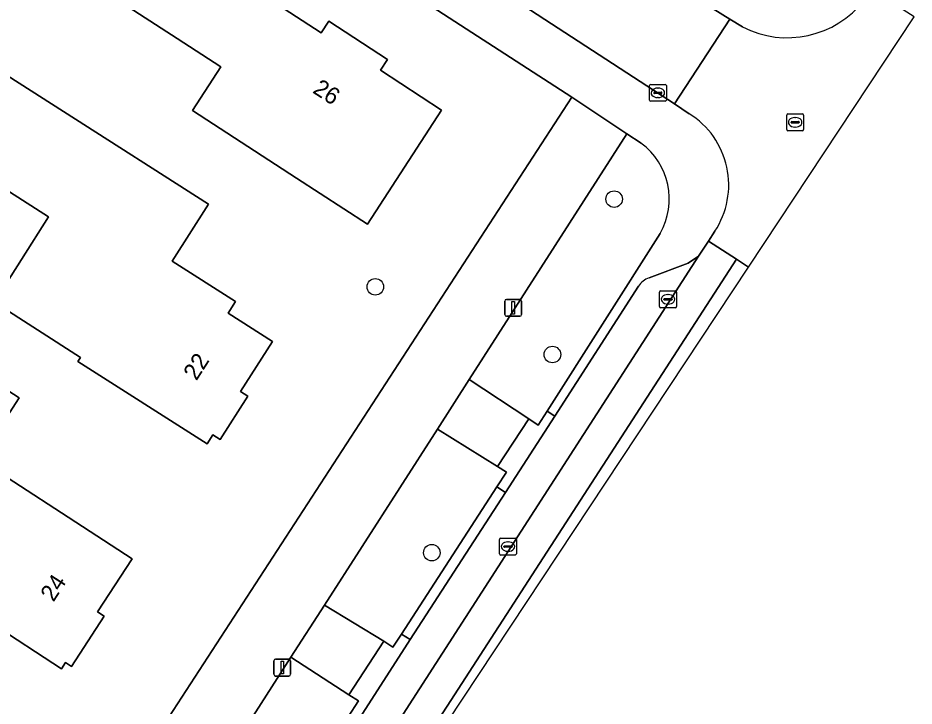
# Model space of a CAD drawing. Extents: x 161139 to 161601, y 381708 to 382245.
# Drawn here: x 161442 to 161495.1, y 381929.2 to 381969.9 of the extents above; entities that cross this region are included whole.
import ezdxf

# ---------------------------------------------------------------- set-up
doc = ezdxf.new("R2010")
doc.units = 0
for name, color, linetype in [('IMGEO_Boom', 7, 'Continuous'), ('IMGEO_Erf', 7, 'Continuous'), ('IMGEO_Groenvoorziening', 7, 'Continuous'), ('IMGEO_Kolk', 7, 'Continuous'), ('IMGEO_Lichtmast', 7, 'Continuous'), ('IMGEO_Pand', 7, 'Continuous'), ('IMGEO_Pand_nummerreeks', 7, 'Continuous'), ('IMGEO_Parkeervlak_open', 7, 'Continuous'), ('IMGEO_Rijbaan_lokaal_gesloten', 7, 'Continuous'), ('IMGEO_Rijbaan_lokaal_open', 7, 'Continuous'), ('IMGEO_Rioolput', 7, 'Continuous'), ('IMGEO_Voetpad_open', 7, 'Continuous')]:
    doc.layers.add(name, color=color, linetype=linetype)

msp = doc.modelspace()

# ---------------------------------------------------------------- linework, layer by layer
at = {"layer": 'IMGEO_Boom'}
for centre in [(161477.319, 381959.197), (161463.178, 381954.004), (161473.664, 381949.997), (161466.524, 381938.263)]:
    msp.add_circle(centre, 0.489, dxfattribs=at)
at = {"layer": 'IMGEO_Erf'}
msp.add_lwpolyline([(161430.666, 381897.334), (161474.804, 381965.241), (161421.048, 382000)], dxfattribs=at)
for points in [[(161449.552, 381975.564), (161456.544, 381971.017), (161456.666, 381971.205), (161459.982, 381969.048), (161460.425, 381969.728), (161463.898, 381967.469), (161463.48, 381966.826), (161467.104, 381964.469), (161462.709, 381957.712), (161458.518, 381960.439), (161452.348, 381964.452), (161454.026, 381967.032), (161451.457, 381968.703), (161446.982, 381971.614)], [(161436.113, 381969.868), (161453.299, 381958.899), (161451.149, 381955.529), (161454.905, 381953.132), (161454.472, 381952.454), (161457.1, 381950.777), (161455.205, 381947.808), (161455.632, 381947.535), (161453.984, 381944.959), (161453.554, 381945.234), (161453.216, 381944.706), (161445.564, 381949.575), (161445.725, 381949.828), (161440.611, 381953.092), (161443.837, 381958.147), (161436.391, 381962.9), (161436.43, 381962.961), (161433.072, 381965.105)], [(161426.297, 381954.589), (161427.683, 381956.735), (161435.118, 381951.933), (161442.093, 381947.428), (161439.732, 381943.773), (161444.594, 381940.628), (161448.782, 381937.896), (161446.736, 381934.759), (161447.131, 381934.501), (161445.19, 381931.527), (161444.844, 381931.753), (161444.6, 381931.379), (161440.412, 381934.111), (161435.544, 381937.289), (161436.694, 381939.07), (161433.36, 381941.223), (161435.339, 381944.288), (161431.697, 381946.644), (161432.758, 381948.284), (161433.731, 381949.788)]]:
    msp.add_lwpolyline(points, close=True, dxfattribs=at)
at = {"layer": 'IMGEO_Groenvoorziening'}
msp.add_lwpolyline([(161478.909, 381962.515), (161478.068, 381963.057), (161468.743, 381948.527), (161472.261, 381946.18), (161472.824, 381945.809), (161473.355, 381946.644), (161480.039, 381957.163)], dxfattribs=at)
for points in [[(161464.222, 381932.663), (161464.734, 381933.448), (161470.374, 381942.161), (161470.955, 381943.032), (161470.422, 381943.36), (161466.851, 381945.579), (161460.162, 381935.157), (161463.677, 381933.019)], [(161455.625, 381919.283), (161456.096, 381920.062), (161461.576, 381928.548), (161462.19, 381929.494), (161461.612, 381929.854), (161458.183, 381932.073), (161451.6, 381921.815), (161455.089, 381919.607)]]:
    msp.add_lwpolyline(points, close=True, dxfattribs=at)
msp.add_arc((161476.493, 381959.21), 4.094, 330.0081, 53.8361, dxfattribs=at)
at = {"layer": 'IMGEO_Kolk'}
for p, q in [((161479.408, 381965.065), (161479.408, 381965.917)), ((161479.483, 381965.991), (161480.335, 381965.991)), ((161480.409, 381965.917), (161480.409, 381965.065)), ((161479.667, 381965.485), (161479.667, 381965.497)), ((161480.105, 381965.448), (161479.707, 381965.448)), ((161479.71, 381965.534), (161480.108, 381965.534)), ((161479.896, 381965.771), (161479.921, 381965.771)), ((161480.151, 381965.497), (161480.151, 381965.485)), ((161480.335, 381964.991), (161479.483, 381964.991)), ((161479.919, 381965.211), (161479.894, 381965.211)), ((161480.008, 381952.84), (161480.008, 381953.692)), ((161480.083, 381953.766), (161480.935, 381953.766)), ((161481.009, 381953.692), (161481.009, 381952.84)), ((161480.267, 381953.26), (161480.267, 381953.272)), ((161480.705, 381953.223), (161480.307, 381953.223)), ((161480.31, 381953.309), (161480.708, 381953.309)), ((161480.496, 381953.546), (161480.521, 381953.546)), ((161480.751, 381953.272), (161480.751, 381953.26)), ((161480.935, 381952.766), (161480.083, 381952.766)), ((161480.519, 381952.986), (161480.494, 381952.986)), ((161470.529, 381938.199), (161470.529, 381939.051)), ((161470.604, 381939.125), (161471.456, 381939.125)), ((161471.017, 381938.905), (161471.042, 381938.905)), ((161471.53, 381939.051), (161471.53, 381938.199)), ((161470.788, 381938.619), (161470.788, 381938.631)), ((161471.226, 381938.582), (161470.828, 381938.582)), ((161470.831, 381938.668), (161471.229, 381938.668)), ((161471.04, 381938.345), (161471.015, 381938.345)), ((161471.272, 381938.631), (161471.272, 381938.619)), ((161471.456, 381938.125), (161470.604, 381938.125))]:
    msp.add_line(p, q, dxfattribs=at)
for points in [[(161479.408, 381965.065), (161479.408, 381965.917)], [(161479.483, 381965.991), (161480.335, 381965.991)], [(161480.409, 381965.917), (161480.409, 381965.065)], [(161480.335, 381964.991), (161479.483, 381964.991)], [(161480.008, 381952.84), (161480.008, 381953.692)], [(161480.083, 381953.766), (161480.935, 381953.766)], [(161481.009, 381953.692), (161481.009, 381952.84)], [(161480.935, 381952.766), (161480.083, 381952.766)], [(161470.529, 381938.199), (161470.529, 381939.051)], [(161470.604, 381939.125), (161471.456, 381939.125)], [(161471.53, 381939.051), (161471.53, 381938.199)], [(161471.456, 381938.125), (161470.604, 381938.125)]]:
    msp.add_lwpolyline(points, dxfattribs=at)
for centre, radius, start, end in [((161479.485, 381965.915), 0.0765, 91.552, 178.448), ((161479.485, 381965.915), 0.0765, 91.552, 178.448), ((161480.333, 381965.915), 0.0765, 1.552, 88.448), ((161480.333, 381965.915), 0.0765, 1.552, 88.448), ((161479.707, 381965.494), 0.0403, 85.8775, 175.7526), ((161479.704, 381965.484), 0.0366, 178.938, 274.7102), ((161480.108, 381965.491), 0.043, 264.8664, 352.4533), ((161480.112, 381965.496), 0.0386, 1.7309, 96.639), ((161479.485, 381965.067), 0.0765, 181.552, 268.448), ((161479.485, 381965.067), 0.0765, 181.552, 268.448), ((161480.333, 381965.067), 0.0765, 271.552, 358.448), ((161480.333, 381965.067), 0.0765, 271.552, 358.448), ((161480.085, 381953.69), 0.0765, 91.552, 178.448), ((161480.085, 381953.69), 0.0765, 91.552, 178.448), ((161480.933, 381953.69), 0.0765, 1.552, 88.448), ((161480.933, 381953.69), 0.0765, 1.552, 88.448), ((161480.307, 381953.269), 0.0403, 85.8775, 175.7526), ((161480.304, 381953.259), 0.0366, 178.938, 274.7102), ((161480.708, 381953.266), 0.043, 264.8664, 352.4533), ((161480.712, 381953.271), 0.0386, 1.7309, 96.639), ((161480.085, 381952.842), 0.0765, 181.552, 268.448), ((161480.085, 381952.842), 0.0765, 181.552, 268.448), ((161480.933, 381952.842), 0.0765, 271.552, 358.448), ((161480.933, 381952.842), 0.0765, 271.552, 358.448), ((161470.606, 381939.049), 0.0765, 91.552, 178.448), ((161470.606, 381939.049), 0.0765, 91.552, 178.448), ((161471.454, 381939.049), 0.0765, 1.552, 88.448), ((161471.454, 381939.049), 0.0765, 1.552, 88.448), ((161470.828, 381938.628), 0.0403, 85.8775, 175.7526), ((161470.825, 381938.618), 0.0366, 178.938, 274.7102), ((161471.229, 381938.625), 0.043, 264.8664, 352.4533), ((161471.233, 381938.63), 0.0386, 1.7309, 96.639), ((161470.606, 381938.201), 0.0765, 181.552, 268.448), ((161470.606, 381938.201), 0.0765, 181.552, 268.448), ((161471.454, 381938.201), 0.0765, 271.552, 358.448), ((161471.454, 381938.201), 0.0765, 271.552, 358.448)]:
    msp.add_arc(centre, radius, start, end, dxfattribs=at)
for centre, major_axis, ratio, start_param, end_param in [((161479.895, 381965.491), (-0.387, 0.002), 0.722429, 4.712389, 7.853982), ((161479.92, 381965.491), (-0.39, 0.002), 0.717154, 1.570796, 4.712389), ((161480.495, 381953.266), (-0.387, 0.002), 0.722429, 4.712389, 7.853982), ((161480.52, 381953.266), (-0.39, 0.002), 0.717154, 1.570796, 4.712389), ((161471.016, 381938.625), (-0.387, 0.002), 0.722429, 4.712389, 7.853982), ((161471.041, 381938.625), (-0.39, 0.002), 0.717154, 1.570796, 4.712389)]:
    msp.add_ellipse(centre, major_axis=major_axis, ratio=ratio, start_param=start_param, end_param=end_param, dxfattribs=at)
at = {"layer": 'IMGEO_Lichtmast'}
for p, q in [((161470.846, 381952.361), (161470.846, 381953.161)), ((161470.846, 381953.161), (161470.846, 381952.361)), ((161470.946, 381953.261), (161471.736, 381953.261)), ((161471.736, 381953.261), (161470.946, 381953.261)), ((161471.836, 381953.161), (161471.836, 381952.361)), ((161471.836, 381952.361), (161471.836, 381953.161)), ((161471.736, 381952.261), (161470.946, 381952.261)), ((161470.946, 381952.261), (161471.736, 381952.261)), ((161457.276, 381931.961), (161458.066, 381931.961)), ((161458.066, 381931.961), (161457.276, 381931.961)), ((161457.176, 381931.061), (161457.176, 381931.861)), ((161457.176, 381931.861), (161457.176, 381931.061)), ((161458.166, 381931.861), (161458.166, 381931.061)), ((161458.166, 381931.061), (161458.166, 381931.861)), ((161458.066, 381930.961), (161457.276, 381930.961)), ((161457.276, 381930.961), (161458.066, 381930.961))]:
    msp.add_line(p, q, dxfattribs=at)
for points in [[(161471.266, 381953.136), (161471.416, 381953.136), (161471.416, 381952.386), (161471.266, 381952.386), (161471.266, 381953.136)], [(161457.596, 381931.836), (161457.746, 381931.836), (161457.746, 381931.086), (161457.596, 381931.086), (161457.596, 381931.836)]]:
    msp.add_lwpolyline(points, dxfattribs=at)
for centre, start, end in [((161470.946, 381953.161), 90, 180), ((161470.946, 381953.161), 90, 180), ((161471.736, 381953.161), 0, 90), ((161471.736, 381953.161), 360, 90), ((161470.946, 381952.361), 180, 270), ((161470.946, 381952.361), 180, 270), ((161471.736, 381952.361), 270, 0), ((161471.736, 381952.361), 270, 0), ((161457.276, 381931.861), 90, 180), ((161457.276, 381931.861), 90, 180), ((161458.066, 381931.861), 0, 90), ((161458.066, 381931.861), 360, 90), ((161457.276, 381931.061), 180, 270), ((161457.276, 381931.061), 180, 270), ((161458.066, 381931.061), 270, 0), ((161458.066, 381931.061), 270, 0)]:
    msp.add_arc(centre, 0.1, start, end, dxfattribs=at)
at = {"layer": 'IMGEO_Pand'}
for points in [[(161458.518, 381960.439), (161462.709, 381957.712), (161467.104, 381964.469), (161463.48, 381966.826), (161463.898, 381967.469), (161460.425, 381969.728), (161459.982, 381969.048), (161456.666, 381971.205), (161456.544, 381971.017), (161449.552, 381975.564), (161446.982, 381971.614), (161451.457, 381968.703), (161454.026, 381967.032), (161452.348, 381964.452)], [(161453.299, 381958.899), (161436.113, 381969.868), (161433.072, 381965.105), (161436.43, 381962.961), (161436.391, 381962.9), (161443.837, 381958.147), (161440.611, 381953.092), (161445.725, 381949.828), (161445.564, 381949.575), (161453.216, 381944.706), (161453.554, 381945.234), (161453.984, 381944.959), (161455.632, 381947.535), (161455.205, 381947.808), (161457.1, 381950.777), (161454.472, 381952.454), (161454.905, 381953.132), (161451.149, 381955.529)], [(161439.732, 381943.773), (161442.093, 381947.428), (161435.118, 381951.933), (161427.683, 381956.735), (161426.297, 381954.589), (161433.731, 381949.788), (161432.758, 381948.284), (161431.697, 381946.644), (161435.339, 381944.288), (161433.36, 381941.223), (161436.694, 381939.07), (161435.544, 381937.289), (161440.412, 381934.111), (161444.6, 381931.379), (161444.844, 381931.753), (161445.19, 381931.527), (161447.131, 381934.501), (161446.736, 381934.759), (161448.782, 381937.896), (161444.594, 381940.628)]]:
    msp.add_lwpolyline(points, close=True, dxfattribs=at)
at = {"layer": 'IMGEO_Parkeervlak_open'}
for points in [[(161442.845, 381894.672), (161445.595, 381898.855), (161482.323, 381955.826)], [(161482.323, 381955.826), (161481.705, 381955.398), (161479.385, 381954.532)], [(161478.765, 381954.039), (161473.808, 381946.346), (161470.887, 381941.819), (161465.235, 381933.121), (161462.089, 381928.215), (161456.613, 381919.75), (161453.345, 381914.652), (161442.912, 381898.524)]]:
    msp.add_lwpolyline(points, dxfattribs=at)
msp.add_arc((161479.728, 381953.464), 1.122, 107.8191, 149.1616, dxfattribs=at)
at = {"layer": 'IMGEO_Rijbaan_lokaal_gesloten'}
msp.add_lwpolyline([(161484.559, 381955.638), (161482.913, 381956.712), (161482.323, 381955.826), (161445.595, 381898.855), (161442.845, 381894.672), (161442.78, 381894.574), (161442.641, 381894.349), (161442.292, 381893.851), (161443.88, 381892.8)], close=True, dxfattribs=at)
at = {"layer": 'IMGEO_Rijbaan_lokaal_open'}
for points in [[(161388.068, 382025.069), (161398.439, 382018.395), (161402.555, 382015.697), (161408.287, 382012.005), (161423.318, 382002.239), (161430.314, 381997.713), (161443.856, 381988.93), (161450.889, 381984.377), (161471.977, 381970.646), (161480.897, 381964.849), (161484.169, 381969.847), (161479.648, 381972.672), (161478.162, 381973.768), (161471.247, 381978.26)], [(161485.274, 381955.176), (161495.077, 381969.984), (161494.211, 381970.546), (161492.536, 381971.604), (161492.126, 381970.984)], [(161484.928, 381969.392), (161484.169, 381969.847), (161480.897, 381964.849), (161481.77, 381964.253)], [(161483.28, 381957.292), (161482.913, 381956.712), (161484.559, 381955.638), (161485.274, 381955.176)]]:
    msp.add_lwpolyline(points, dxfattribs=at)
msp.add_lwpolyline([(161443.951, 381892.753), (161485.274, 381955.176), (161484.559, 381955.638), (161443.88, 381892.8)], close=True, dxfattribs=at)
for centre, radius, start, end in [((161487.568, 381974.524), 5.772, 242.7809, 322.1621), ((161479.13, 381960.036), 4.975, 326.5276, 57.9507)]:
    msp.add_arc(centre, radius, start, end, dxfattribs=at)
at = {"layer": 'IMGEO_Rioolput'}
for p, q in [((161487.535, 381963.32), (161487.535, 381964.172)), ((161487.61, 381964.246), (161488.462, 381964.246)), ((161487.837, 381963.789), (161488.235, 381963.789)), ((161488.023, 381964.026), (161488.048, 381964.026)), ((161488.536, 381964.172), (161488.536, 381963.32)), ((161488.462, 381963.246), (161487.61, 381963.246)), ((161487.794, 381963.74), (161487.794, 381963.752)), ((161488.232, 381963.703), (161487.834, 381963.703)), ((161488.046, 381963.466), (161488.021, 381963.466)), ((161488.278, 381963.752), (161488.278, 381963.74))]:
    msp.add_line(p, q, dxfattribs=at)
for points in [[(161487.535, 381963.32), (161487.535, 381964.172)], [(161487.61, 381964.246), (161488.462, 381964.246)], [(161488.536, 381964.172), (161488.536, 381963.32)], [(161488.462, 381963.246), (161487.61, 381963.246)]]:
    msp.add_lwpolyline(points, dxfattribs=at)
for centre, radius, start, end in [((161487.612, 381964.17), 0.0765, 91.552, 178.448), ((161487.612, 381964.17), 0.0765, 91.552, 178.448), ((161487.834, 381963.749), 0.0403, 85.8775, 175.7526), ((161488.239, 381963.751), 0.0386, 1.7309, 96.639), ((161488.46, 381964.17), 0.0765, 1.552, 88.448), ((161488.46, 381964.17), 0.0765, 1.552, 88.448), ((161487.612, 381963.322), 0.0765, 181.552, 268.448), ((161487.612, 381963.322), 0.0765, 181.552, 268.448), ((161487.831, 381963.739), 0.0366, 178.938, 274.7102), ((161488.235, 381963.746), 0.043, 264.8664, 352.4533), ((161488.46, 381963.322), 0.0765, 271.552, 358.448), ((161488.46, 381963.322), 0.0765, 271.552, 358.448)]:
    msp.add_arc(centre, radius, start, end, dxfattribs=at)
for centre, major_axis, ratio, start_param, end_param in [((161488.022, 381963.746), (-0.387, 0.002), 0.722429, 4.712389, 7.853982), ((161488.047, 381963.746), (-0.39, 0.002), 0.717154, 1.570796, 4.712389)]:
    msp.add_ellipse(centre, major_axis=major_axis, ratio=ratio, start_param=start_param, end_param=end_param, dxfattribs=at)
at = {"layer": 'IMGEO_Voetpad_open'}
for points in [[(161306.066, 382074.349), (161421.048, 382000), (161474.804, 381965.241), (161478.068, 381963.057), (161478.909, 381962.515)], [(161481.77, 381964.253), (161480.897, 381964.849), (161471.977, 381970.646), (161450.889, 381984.377), (161443.856, 381988.93), (161430.314, 381997.713), (161423.318, 382002.239), (161408.287, 382012.005), (161402.555, 382015.697), (161398.439, 382018.395)], [(161471.247, 381978.26), (161478.162, 381973.768), (161479.648, 381972.672), (161484.169, 381969.847), (161484.928, 381969.392)], [(161466.851, 381945.579), (161468.743, 381948.527), (161478.068, 381963.057), (161474.804, 381965.241), (161430.666, 381897.334)], [(161480.039, 381957.163), (161473.355, 381946.644), (161473.808, 381946.346), (161478.765, 381954.039)], [(161479.385, 381954.532), (161481.705, 381955.398), (161482.323, 381955.826), (161482.913, 381956.712), (161483.28, 381957.292)], [(161429.313, 381896.994), (161433.377, 381893.414), (161449.423, 381918.424), (161451.6, 381921.815), (161458.183, 381932.073), (161460.162, 381935.157), (161466.851, 381945.579)]]:
    msp.add_lwpolyline(points, dxfattribs=at)
for points in [[(161472.261, 381946.18), (161468.743, 381948.527), (161466.851, 381945.579), (161470.422, 381943.36)], [(161470.887, 381941.819), (161473.808, 381946.346), (161473.355, 381946.644), (161472.824, 381945.809), (161472.261, 381946.18), (161470.422, 381943.36), (161470.955, 381943.032), (161470.374, 381942.161)], [(161465.235, 381933.121), (161470.887, 381941.819), (161470.374, 381942.161), (161464.734, 381933.448)], [(161463.677, 381933.019), (161460.162, 381935.157), (161458.183, 381932.073), (161461.612, 381929.854)], [(161464.734, 381933.448), (161464.222, 381932.663), (161463.677, 381933.019), (161461.612, 381929.854), (161462.19, 381929.494), (161461.576, 381928.548), (161462.089, 381928.215), (161465.235, 381933.121)]]:
    msp.add_lwpolyline(points, close=True, dxfattribs=at)
for centre, radius, start, end in [((161487.568, 381974.524), 5.772, 242.7809, 322.1621), ((161479.13, 381960.036), 4.975, 326.5276, 57.9507), ((161476.493, 381959.21), 4.094, 330.0081, 53.8361), ((161479.728, 381953.464), 1.122, 107.8191, 149.1616)]:
    msp.add_arc(centre, radius, start, end, dxfattribs=at)

# ---------------------------------------------------------------- texts
at = {"layer": 'IMGEO_Pand_nummerreeks'}
for s, rotation, p in [('26', 327.1645, (161459.413, 381965.529)), ('22', 57.3932, (161452.588, 381948.401)), ('24', 57.313, (161444.124, 381935.303))]:
    msp.add_text(s, height=1, rotation=rotation, dxfattribs=at).set_placement(p)

doc.saveas('drawing.dxf')
